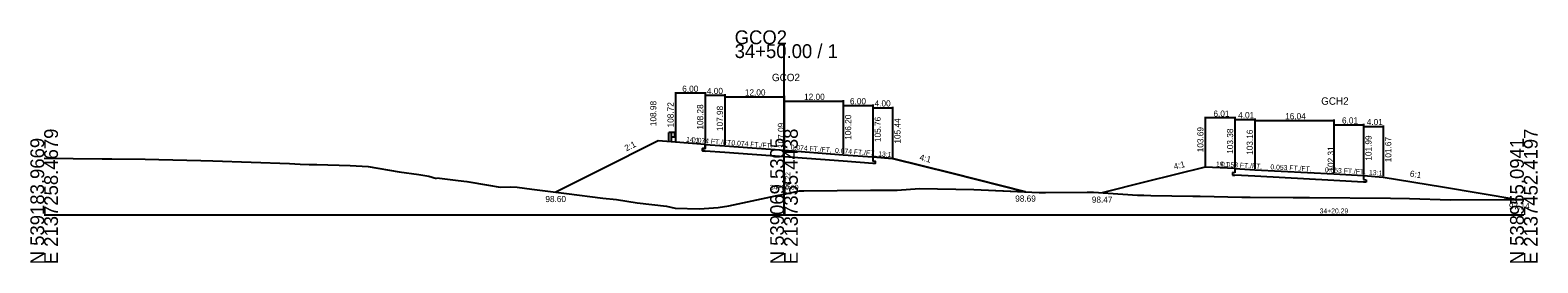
# Model space of a CAD drawing. Extents: x -14327 to 8886, y -10 to 39048.
# Drawn here: x 997.2 to 1302.8, y 8990.3 to 9037.4 of the extents above; entities that cross this region are included whole.
import ezdxf

# ---------------------------------------------------------------- set-up
doc = ezdxf.new("R2010")
doc.units = 0
for name, color, linetype in [('Level 1', 7, 'Continuous'), ('Level 20', 7, 'Continuous'), ('Level 5', 7, 'Continuous'), ('Level 53', 7, 'Continuous'), ('Level 54', 7, 'Continuous'), ('Level 55', 7, 'Continuous'), ('Level 7', 7, 'Continuous'), ('RD_GPK_XS_Cell', 7, 'Continuous'), ('RD_XS_EwShp', 7, 'Continuous'), ('RD_XS_ExGround', 7, 'Continuous'), ('RD_XS_Pave', 7, 'Continuous'), ('RD_XS_TX_Baseline', 7, 'Continuous'), ('RD_XS_TX_Elev_EX', 7, 'Continuous'), ('RD_XS_TX_Elev_PR', 7, 'Continuous'), ('RD_XS_TX_Station', 7, 'Continuous')]:
    doc.layers.add(name, color=color, linetype=linetype)

msp = doc.modelspace()

# ---------------------------------------------------------------- linework, layer by layer
at = {"layer": 'Level 1'}
for p, q in [((1126.66, 9014.72), (1126.66, 9016.71)), ((1127.22, 9016.71), (1126.66, 9016.71)), ((1127.22, 9014.72), (1127.22, 9016.71)), ((1127.77, 9016.71), (1127.22, 9016.71)), ((1127.77, 9015.73), (1127.22, 9015.73)), ((1127.77, 9016.71), (1127.77, 9015.73)), ((1127.85, 9016.63), (1127.77, 9016.65)), ((1127.85, 9015.81), (1127.77, 9015.8)), ((1127.84, 9016.3), (1127.84, 9016.14)), ((1127.98, 9016.54), (1127.86, 9016.63)), ((1127.98, 9016.43), (1127.86, 9016.34)), ((1127.98, 9016.01), (1127.86, 9016.1)), ((1127.98, 9015.91), (1127.86, 9015.81))]:
    msp.add_line(p, q, dxfattribs=at)
for centre, radius, start, end in [((1127.91, 9016.3), 0.0651, 135, 180), ((1127.91, 9016.14), 0.0651, 180, 237.0105), ((1127.85, 9016.61), 0.026, 50.9495, 90), ((1127.85, 9015.83), 0.026, 270, 309.0504), ((1127.93, 9016.49), 0.0651, 309.0337, 50.9664), ((1127.93, 9015.96), 0.0651, 309.0337, 50.9664)]:
    msp.add_arc(centre, radius, start, end, dxfattribs=at)
at = {"layer": 'Level 20'}
for p, q in [((1235.42, 9019.84), (1235.42, 9009.89)), ((1241.43, 9019.64), (1235.42, 9019.64)), ((1241.43, 9019.84), (1241.43, 9009.58)), ((1241.43, 9019.53), (1241.43, 9009.58)), ((1241.43, 9019.33), (1245.44, 9019.33)), ((1245.44, 9019.53), (1245.44, 9009.36)), ((1245.44, 9019.31), (1245.44, 9009.36)), ((1245.44, 9019.11), (1261.48, 9019.11)), ((1261.48, 9019.31), (1261.48, 9008.51)), ((1261.48, 9018.46), (1261.48, 9008.51)), ((1261.48, 9018.26), (1267.5, 9018.26)), ((1267.5, 9018.46), (1267.5, 9008.19)), ((1267.5, 9018.14), (1267.5, 9008.19)), ((1267.5, 9017.94), (1271.51, 9017.94)), ((1271.51, 9018.14), (1271.51, 9007.87)), ((1235.42, 9009.69), (1223.39, 9006.69)), ((1241.43, 9009.38), (1235.42, 9009.69)), ((1240.93, 9008.57), (1240.93, 9008.07)), ((1241.43, 9008.54), (1240.93, 9008.57)), ((1241.43, 9009.38), (1241.43, 9008.54)), ((1241.43, 9009.38), (1245.44, 9009.16)), ((1245.44, 9009.16), (1261.48, 9008.31)), ((1223.39, 9006.69), (1214.49, 9004.47)), ((1240.93, 9008.07), (1241.43, 9008.04)), ((1245.44, 9007.83), (1241.43, 9008.04)), ((1261.48, 9006.98), (1245.44, 9007.83)), ((1261.48, 9008.31), (1267.5, 9007.99)), ((1267.5, 9006.66), (1261.48, 9006.98)), ((1267.5, 9007.99), (1267.5, 9007.16)), ((1267.5, 9007.99), (1271.51, 9007.67)), ((1267.5, 9007.16), (1268, 9007.13)), ((1268, 9006.63), (1267.5, 9006.66)), ((1268, 9007.13), (1268, 9006.63)), ((1271.51, 9007.67), (1283.53, 9005.67)), ((1283.53, 9005.67), (1298.79, 9003.14))]:
    msp.add_line(p, q, dxfattribs=at)
at = {"layer": 'Level 5'}
for p, q in [((1133.5, 9013.48), (1133.5, 9012.98)), ((1134, 9013.44), (1133.5, 9013.48)), ((1133.5, 9012.98), (1134, 9012.94)), ((1134, 9014.28), (1134, 9013.44)), ((1138, 9012.65), (1134, 9012.94)), ((1150, 9011.76), (1138, 9012.65)), ((1162, 9010.87), (1150, 9011.76)), ((1168, 9011.76), (1168, 9010.93)), ((1168, 9010.43), (1162, 9010.87)), ((1168, 9010.93), (1168.5, 9010.89)), ((1168.5, 9010.39), (1168, 9010.43)), ((1168.5, 9010.89), (1168.5, 9010.39))]:
    msp.add_line(p, q, dxfattribs=at)
at = {"layer": 'Level 54'}
for p, q in [((1128, 9024.87), (1128, 9014.92)), ((1134, 9024.67), (1128, 9024.67)), ((1134, 9024.87), (1134, 9014.48)), ((1134, 9024.43), (1134, 9014.48)), ((1134, 9024.23), (1138, 9024.23)), ((1138, 9024.43), (1138, 9014.18)), ((1138, 9024.13), (1138, 9014.18)), ((1138, 9023.93), (1150, 9023.93)), ((1150, 9024.13), (1150, 9013.29)), ((1150, 9023.24), (1150, 9013.29)), ((1150, 9023.04), (1162, 9023.04)), ((1162, 9023.24), (1162, 9012.4)), ((1162, 9022.35), (1162, 9012.4)), ((1162, 9022.15), (1168, 9022.15)), ((1168, 9022.35), (1168, 9011.96)), ((1168, 9021.91), (1168, 9011.96)), ((1168, 9021.71), (1172, 9021.71)), ((1172, 9021.91), (1172, 9011.64))]:
    msp.add_line(p, q, dxfattribs=at)
at = {"layer": 'Level 7'}
for p, q in [((1124.5, 9014.98), (1112.5, 9008.98)), ((1128, 9014.72), (1124.5, 9014.98)), ((1134, 9014.28), (1128, 9014.72)), ((1168, 9011.76), (1172, 9011.44)), ((1112.5, 9008.98), (1103.75, 9004.6)), ((1172, 9011.44), (1184, 9008.44)), ((1184, 9008.44), (1198.99, 9004.69))]:
    msp.add_line(p, q, dxfattribs=at)
at = {"layer": 'RD_GPK_XS_Cell'}
for p, q in [((1150, 9000), (1150, 9034.57)), ((1000, 9000), (1150, 9000)), ((1150, 9000), (1300, 9000))]:
    msp.add_line(p, q, dxfattribs=at)
at = {"layer": 'RD_XS_EwShp'}
msp.add_lwpolyline([(1134, 9014.28), (1128, 9014.72), (1124.5, 9014.98), (1112.5, 9008.98), (1103.75, 9004.6), (1105.9, 9004.33), (1113.29, 9003.43), (1116.01, 9003.13), (1120.21, 9002.47), (1126.17, 9001.79), (1127.94, 9001.39), (1132.9, 9001.26), (1136.63, 9001.48), (1138.82, 9001.86), (1148.26, 9003.86), (1150, 9004.22), (1153.11, 9004.85), (1153.99, 9004.89), (1167.55, 9005.01), (1172.96, 9005.01), (1177.45, 9005.33), (1188.51, 9005.16), (1198.99, 9004.69), (1184, 9008.44), (1172, 9011.44), (1168, 9011.76), (1168, 9010.93), (1168.5, 9010.89), (1168.5, 9010.39), (1168, 9010.43), (1162, 9010.87), (1150, 9011.76), (1138, 9012.65), (1134, 9012.94), (1133.5, 9012.98), (1133.5, 9013.48), (1134, 9013.44)], close=True, dxfattribs=at)
at = {"layer": 'RD_XS_ExGround'}
for p, q in [((1000, 9011.52), (1011.77, 9011.38)), ((1011.77, 9011.38), (1013.7, 9011.35)), ((1013.7, 9011.35), (1020.5, 9011.26)), ((1020.5, 9011.26), (1023.22, 9011.2)), ((1023.22, 9011.2), (1031.79, 9011.03)), ((1031.79, 9011.03), (1034.21, 9010.95)), ((1034.21, 9010.95), (1049.76, 9010.43)), ((1049.76, 9010.43), (1051.89, 9010.31)), ((1051.89, 9010.31), (1053.73, 9010.2)), ((1053.73, 9010.2), (1055.29, 9010.21)), ((1055.29, 9010.21), (1062.06, 9010.03)), ((1062.06, 9010.03), (1065.72, 9009.8)), ((1065.72, 9009.8), (1071.99, 9008.75)), ((1071.99, 9008.75), (1075.94, 9008.19)), ((1075.94, 9008.19), (1078, 9007.83)), ((1078, 9007.83), (1079.54, 9007.4)), ((1079.54, 9007.4), (1079.64, 9007.53)), ((1079.64, 9007.53), (1083.97, 9006.97)), ((1083.97, 9006.97), (1085.69, 9006.74)), ((1085.69, 9006.74), (1090.06, 9006.06)), ((1090.06, 9006.06), (1092.45, 9005.61)), ((1092.45, 9005.61), (1094.5, 9005.66)), ((1094.5, 9005.66), (1095.87, 9005.6)), ((1095.87, 9005.6), (1098.84, 9005.22)), ((1098.84, 9005.22), (1105.9, 9004.33)), ((1105.9, 9004.33), (1113.29, 9003.43)), ((1113.29, 9003.43), (1116.01, 9003.13)), ((1116.01, 9003.13), (1120.21, 9002.47)), ((1120.21, 9002.47), (1126.17, 9001.79)), ((1138.82, 9001.86), (1148.26, 9003.86)), ((1148.26, 9003.86), (1150, 9004.22)), ((1150, 9004.22), (1153.11, 9004.85)), ((1153.11, 9004.85), (1153.99, 9004.89)), ((1153.99, 9004.89), (1167.55, 9005.01)), ((1167.55, 9005.01), (1172.96, 9005.01)), ((1172.96, 9005.01), (1177.45, 9005.33)), ((1177.45, 9005.33), (1188.51, 9005.16)), ((1188.51, 9005.16), (1201.73, 9004.57)), ((1201.73, 9004.57), (1203.01, 9004.55)), ((1203.01, 9004.55), (1211.44, 9004.6)), ((1211.44, 9004.6), (1212.78, 9004.58)), ((1212.78, 9004.58), (1221.65, 9004.02)), ((1221.65, 9004.02), (1222.97, 9004.01)), ((1222.97, 9004.01), (1224.4, 9003.96)), ((1224.4, 9003.96), (1232.86, 9003.82)), ((1232.86, 9003.82), (1234.37, 9003.83)), ((1234.37, 9003.83), (1242.83, 9003.62)), ((1242.83, 9003.62), (1244.5, 9003.62)), ((1244.5, 9003.62), (1253.2, 9003.56)), ((1253.2, 9003.56), (1256.53, 9003.51)), ((1256.53, 9003.51), (1272.98, 9003.39)), ((1272.98, 9003.39), (1276.79, 9003.32)), ((1276.79, 9003.32), (1285.13, 9003.07)), ((1285.13, 9003.07), (1296.01, 9003.1)), ((1296.01, 9003.1), (1300, 9003.15)), ((1126.17, 9001.79), (1127.94, 9001.39)), ((1127.94, 9001.39), (1132.9, 9001.26)), ((1132.9, 9001.26), (1136.63, 9001.48)), ((1136.63, 9001.48), (1138.82, 9001.86))]:
    msp.add_line(p, q, dxfattribs=at)
at = {"layer": 'RD_XS_Pave'}
for p, q in [((1134, 9014.28), (1138, 9013.98)), ((1138, 9013.98), (1150, 9013.09)), ((1150, 9013.09), (1162, 9012.2)), ((1162, 9012.2), (1168, 9011.76))]:
    msp.add_line(p, q, dxfattribs=at)

# ---------------------------------------------------------------- texts
at = {"layer": 'Level 20'}
for s, height, p in [('GCH2', 1.5, (1258.91, 9022.31)), ('GCH2', 1.5, (1258.91, 9022.31)), ('6.01', 1.25, (1237.07, 9019.89)), ('4.01', 1.25, (1242.08, 9019.58)), ('16.04', 1.25, (1251.61, 9019.36)), ('6.01', 1.25, (1263.13, 9018.51)), ('4.01', 1.25, (1268.15, 9018.19)), ('98.47', 1.25, (1212.41, 9002.47)), ('97.14', 1.25, (1296.99, 9001.14)), ('34+20.29', 1, (1258.6, 9000.31)), ('34+20.29', 1, (1258.6, 9000.31))]:
    msp.add_text(s, height=height, dxfattribs=at).set_placement(p)
for s, height, rotation, p in [('103.69', 1.25, 90, (1235.04, 9012.69)), ('103.38', 1.25, 90, (1241.06, 9012.38)), ('103.16', 1.25, 90, (1245.06, 9012.16)), ('101.99', 1.25, 90, (1269.12, 9010.99)), ('101.67', 1.25, 90, (1273.13, 9010.67)), (' 102.31', 1.25, 90, (1261.48, 9008.31)), (' 102.31', 1.25, 90, (1261.48, 9008.31)), ('4:1', 1.25, 14.0044, (1229.16, 9009.16)), ('19:1', 1, 356.9713, (1237.54, 9009.83)), ('0.053 FT./FT.', 1, 356.9642, (1238.57, 9009.78)), ('0.053 FT./FT.', 1, 356.9649, (1248.6, 9009.25)), ('0.053 FT./FT.', 1, 356.9657, (1259.62, 9008.66)), ('13:1', 1, 355.4372, (1268.57, 9008.16)), ('6:1', 1.25, 350.5604, (1276.82, 9007.8))]:
    msp.add_text(s, height=height, rotation=rotation, dxfattribs=at).set_placement(p)
at = {"layer": 'Level 53'}
for s, rotation, p in [('108.98', 90, (1124.12, 9017.98)), ('108.72', 90, (1127.62, 9017.72)), ('108.28', 90, (1133.62, 9017.28)), ('107.98', 90, (1137.63, 9016.98)), ('106.20', 90, (1163.62, 9015.2)), ('105.76', 90, (1169.62, 9014.76)), ('105.44', 90, (1173.62, 9014.44)), ('2:1', 26.5651, (1118.05, 9012.87)), ('4:1', 345.9638, (1177.39, 9011.12))]:
    msp.add_text(s, height=1.25, rotation=rotation, dxfattribs=at).set_placement(p)
for s, p in [('98.60', (1101.62, 9002.6)), ('98.69', (1196.88, 9002.69))]:
    msp.add_text(s, height=1.25, dxfattribs=at).set_placement(p)
at = {"layer": 'Level 54'}
for s, p in [('6.00', (1129.37, 9024.92)), ('4.00', (1134.37, 9024.48)), ('12.00', (1142.07, 9024.18)), ('12.00', (1154.07, 9023.29)), ('6.00', (1163.37, 9022.4)), ('4.00', (1168.37, 9021.96))]:
    msp.add_text(s, height=1.25, dxfattribs=at).set_placement(p)
at = {"layer": 'Level 55'}
for s, rotation, p in [('14:1', 355.7678, (1130.12, 9014.81)), ('0.074 FT./FT.', 355.7678, (1131.31, 9014.72)), ('0.074 FT./FT.', 355.7678, (1139.31, 9014.13)), ('0.074 FT./FT.', 355.7678, (1151.31, 9013.24)), ('0.074 FT./FT.', 355.7678, (1160.31, 9012.58)), ('13:1', 355.4261, (1169.07, 9011.92))]:
    msp.add_text(s, height=1, rotation=rotation, dxfattribs=at).set_placement(p)
at = {"layer": 'RD_GPK_XS_Cell'}
for s, p in [('GCO2', (1140, 9034.57)), ('34+50.00 / 1', (1140, 9031.77))]:
    msp.add_text(s, height=2.8, dxfattribs=at).set_placement(p)
for s, p in [('N 539183.9669', (1000, 8990)), ('E 2137258.4679', (1002.8, 8990)), ('N 539069.5305', (1150, 8990)), ('E 2137355.4438', (1152.8, 8990)), ('N 538955.0941', (1300, 8990)), ('E 2137452.4197', (1302.8, 8990))]:
    msp.add_text(s, height=2.8, rotation=90, dxfattribs=at).set_placement(p)
at = {"layer": 'RD_XS_TX_Baseline'}
msp.add_text('GCO2', height=1.5, dxfattribs=at).set_placement((1147.55, 9027.09))
at = {"layer": 'RD_XS_TX_Elev_EX'}
msp.add_text('98.22', height=1, rotation=90, dxfattribs=at).set_placement((1151.25, 9005.22))
at = {"layer": 'RD_XS_TX_Elev_PR'}
msp.add_text(' 107.09', height=1.25, rotation=90, dxfattribs=at).set_placement((1150, 9013.09))
at = {"layer": 'RD_XS_TX_Station'}
msp.add_text('34+50.00', height=1, dxfattribs=at).set_placement((1147.15, 9005.09))

doc.saveas('drawing.dxf')
